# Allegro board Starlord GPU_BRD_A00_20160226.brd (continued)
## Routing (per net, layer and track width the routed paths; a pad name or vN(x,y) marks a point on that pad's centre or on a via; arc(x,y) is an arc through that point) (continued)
PWR_VGA_CORE_LGATE2: length 13.8
  TOP w0.254: v3(29.23,9.22) 29.23,9.81 29.2,9.83 v1(29.2,9.88)
  TOP w0.762: PU8206.8 v3(27.89,18.85)
  L6 w0.508: v3(29.23,9.22) 29.17,9.27
  L6 w1.016: v3(27.89,18.85) v3(27.89,13.26) 28.01,13.15 28.01,12.89 29.17,11.73 29.17,9.27
  BOTTOM w0.203: PU8201.17 29.44,8.89 29.23,9.1 v3(29.23,9.22)
  BOTTOM w0.762: PU8208.8 v3(27.89,13.26)
PWR_VGA_CORE_PHASE1: length 10.3
  L6 w1.016: v3(31.28,8.16) 31.8,8.16 35.85,12.21 v3(35.85,12.88)
  BOTTOM w0.203: v3(31.28,8.16) 31.23,8.1 PU8201.20
  BOTTOM w0.508: v3(31.28,8.16) 32.15,9.02 32.19,9.02 32.52,9.35 PC8211.2
  vias: v1(35.22,24.06) v3(32.88,24.18) v3(32.96,23.22) v3(32.93,22.28) v3(32.96,21.21) v3(33.01,20.17) v3(37.58,24.13) v3(37.58,23.24) v3(37.63,22.3) v3(37.68,21.26) v3(37.66,20.3)
PWR_VGA_CORE_PHASE2: length 10.4
  L6 w1.016: v3(28.25,8.02) 26.51,9.76 26.51,10.44 v3(24.02,12.93)
  BOTTOM w0.203: PU8201.16 28.34,8.1 v3(28.25,8.02)
  BOTTOM w0.508: v3(28.25,8.02) 28.25,8.07 28.26,8.08 28.26,8.4 27.4,9.27 27.4,9.35 26.69,10.06 PC8216.2
  vias: v1(24.04,23.93) v3(21.88,24.06) v3(21.88,23.04) v3(21.88,22.03) v3(21.88,21.14) v3(21.88,20.12) v3(26.71,23.8) v3(26.71,22.79) v3(26.71,21.77) v3(26.71,20.88) v3(26.71,19.87)
PWR_VGA_CORE_PSI: length 5.4
  TOP w0.254: v1(31.84,6) 32.45,6 v2(32.48,6.02) 32.71,6.02 32.76,6.07 PC8226.2 PR8259.1 PR8257.2 PR8258.2
  BOTTOM w0.203: PU8201.4 32.35,6.15 v2(32.48,6.02)
PWR_VGA_CORE_REFADJ: length 3.2
  TOP w0.254: v2(31.74,4.3) 32.07,4.63 v1(32.58,4.63)
  BOTTOM w0.203: 31.41,4.63 31.04,5 PU8201.6
  BOTTOM w0.254: PR8222.1 v2(31.74,4.3) 31.41,4.63
PWR_VGA_CORE_REFIN: length 4.4
  TOP w0.254: v1(31.28,4.75) v2(30.65,4.12) 30.85,3.91 PR8209.1 PC8204.1
  BOTTOM w0.254: PR8209.1 30.85,3.91 v2(30.65,4.12) 30.48,4.29 30.43,4.29 30.24,4.48 PU8201.7
PWR_VGA_CORE_RGND: length 14.9
  TOP w0.254: v2(28.36,4.5) 28.36,3.96 28.16,3.76 28.16,3.28 v1(28.16,3.28) 28.16,3.28 28.16,3.06 28.67,2.55 PC8201.1 PC8204.2 PR8209.2 PC8223.2
  BOTTOM w0.254: PR8220.1 22.91,7.69 PR8213.1 PC8217.1 PC8219.2 23.57,4.5 23.92,4.5 24.3,4.12 26.62,4.12 27.1,4.6 27.84,4.6 27.85,4.59 28.26,4.59 v2(28.36,4.5) 28.86,5 PU8201.10
PWR_VGA_CORE_SS: length 2.5
  TOP w0.254: v1(27.04,5.11) 27.07,5.13 v2(27.6,5.13) 27.6,5.78 PC8205.1
  BOTTOM w0.203: PU8201.11 28.03,5.75 27.6,5.32 v2(27.6,5.13)
PWR_VGA_CORE_TON: length 2.6
  TOP w0.254: v1(28.87,4.93) 29.05,4.75 v2(29.05,4.17)
  BOTTOM w0.254: PR8201.2 29.07,4.14 v2(29.05,4.17) 29.12,4.17 29.44,4.48 PU8201.9
PWR_VGA_CORE_TON_1: length 2.7
  BOTTOM w0.254: PR8202.2 28.25,1.57 v1(28.23,1.55) ; PR8202.2 PC8202.2 ; PR8202.2 28.29,2.44 28.96,2.44 PR8201.1
PWR_VGA_CORE_UGATE1: length 17.8
  TOP w0.305: v1(31.92,7.22) v3(32.65,7.22)
  TOP w0.762: PU8204.1 v3(37.8,13.07)
  L6 w1.016: v3(37.8,18.85) v3(37.8,13.07) 37.8,12.36 v3(32.65,7.22)
  BOTTOM w0.203: PU8201.2 32.39,6.95 v3(32.65,7.22)
  BOTTOM w0.762: PU8202.1 v3(37.8,18.85)
PWR_VGA_CORE_UGATE2: length 17.8
  TOP w0.254: v1(27.22,7.8) v3(27.22,7.14)
  TOP w0.762: v3(21.88,18.85) 21.87,18.84 PU8206.1
  L6 w1.016: 22.29,13.2 v3(22.28,13.19) ; 22.29,13.2 22.29,12.86 25.03,10.12 25.03,9.33 v3(27.22,7.14) ; 22.29,13.2 22.29,18.44 v3(21.88,18.85)
  BOTTOM w0.203: v3(27.22,7.14) 27.41,6.95 PU8201.14
  BOTTOM w0.762: PU8208.1 22.28,13.77 v3(22.28,13.19)
PWR_VGA_CORE_VID: length 4.3
  BOTTOM w0.203: 32.27,5.49 32.01,5.75 PU8201.5
  BOTTOM w0.254: 32.27,5.49 33.06,4.7 PC8203.2 PR8207.2 33.42,3.82 v1(33.42,2.92)
PWR_VGA_CORE_VREF: length 3.5
  TOP w0.254: PC8201.2 29.8,4.16 v2(29.84,4.16) 30.06,4.39 v1(30.06,4.68)
  BOTTOM w0.254: PR8206.1 29.96,4.04 v2(29.84,4.16) 29.84,4.17 29.96,4.17 29.84,4.3 PU8201.8
PWR_VGA_CORE_VSNS: length 8
  BOTTOM w0.254: PR8221.1 23.8,7.69 PR8212.2 PC8222.1 PC8219.1 23.95,5.01 24.13,5.01 24.51,4.63 v1(25.19,4.63) 26.41,4.63 27.6,5.82 27.6,5.95 27.8,6.15 PU8201.12
PWR_VGA_SNUB1: length 1.2
  BOTTOM w0.508: PC8206.1 32.68,12.39 PR8216.2
PWR_VGA_SNUB2: length 1.2
  BOTTOM w0.508: PR8215.2 27.43,12.5 PC8218.1
Q7601_G: length 5.7
  BOTTOM w0.102: Q7601.2 50.71,59.95 50.9,59.75 51.32,59.75 51.52,59.95 Q7601.5 53.05,59.95 53.33,60.23 v1(53.33,60.94) 53.33,61.59 53.05,61.87 R7657.2
REFIN_VREF: length 5.1
  TOP w0.254: PC8223.1 32.09,3.44 32.43,3.78 v2(32.43,3.84) 32.53,3.74 32.58,3.74 v1(33.04,3.28)
  BOTTOM w0.254: v2(32.43,3.84) 32.43,3.25 31.74,2.57 PR8222.2 PR8208.2 PR8206.2
RT8812_PVCC: length 3.5
  BOTTOM w0.203: PU8201.18 29.84,9.6 30.22,9.99 PR8223.2
  BOTTOM w0.508: PC8207.1 PR8223.2
SMBC_THERM_NV: length 22.2
  L3 w0.102: v2(50.08,61.45) 49.75,61.45 48.77,60.47 46.43,60.47 45.69,59.73 45.38,59.42 45.38,59.42 44.36,58.4 44.36,57.96 44.36,57.95 44.36,54.13 v2(43.96,53.73)
  BOTTOM w0.089: Q7601.1 49.81,59.3 49.01,60.1 v1(49.01,60.25) 49.01,60.38 v2(50.08,61.45) 50.19,61.45 50.74,61.99 50.74,62.4 RN7601.2 ; v2(43.96,53.73) 43.52,54.16 43.16,54.16 42.98,54.34 39.25,54.34 38.89,53.98 GPU1.D9
SMBD_THERM_NV: length 21.9
  TOP w0.089: v1(51.25,61.83) 51.25,61.8 v2(50.84,61.4)
  L3 w0.102: v2(38.19,54.38) 38.57,54.76 39.92,54.76 41.84,56.67 41.84,58.09 45.79,62.04 50.19,62.04 v2(50.84,61.4)
  BOTTOM w0.089: Q7601.4 51.51,60.6 50.84,61.27 v2(50.84,61.4) 50.97,61.4 51.37,61.8 RN7601.1 ; GPU1.D8 38.19,53.55 v2(38.19,54.38)
SML1_SMBCLK: length 74.8
  TOP w0.089: v1(51.78,58.65) 51.76,58.68 v2(51.17,58.68)
  L3 w0.102: v2(51.17,58.68) 51.17,53.17 50,52 50,45.14 45.63,40.77 45.63,40.77 45.32,40.46 41.29,40.46 40.88,40.05 36.69,40.05 35.59,41.14 31.38,41.14 30.94,40.69 28.12,40.69 27.41,39.98 18.84,39.98 16.73,42.1 16.73,44.48 14.32,46.88 11.8,46.88 9.48,49.2 9.48,51.15 8.89,51.73 7.07,51.73 6.12,52.68 4.26,52.68 v2(3.37,51.79)
  BOTTOM w0.089: GPU3.E3 3.55,51.98 v2(3.37,51.79) ; Q7601.6 52.06,58.91 51.86,58.7 51.2,58.7 v2(51.17,58.68)
SML1_SMBDATA: length 78.1
  TOP w0.089: v1(51.7,60.25) v2(51.11,60.25)
  L3 w0.102: v2(51.11,60.25) 51.11,60.14 50.66,59.69 50.66,53.41 49.47,52.22 49.47,45.37 45.1,40.99 41.07,40.99 40.66,40.58 37.91,40.58 36.46,42.03 31.52,42.03 30.72,41.23 27.9,41.23 27.36,40.69 18.89,40.69 17.26,42.32 17.26,44.7 14.55,47.42 12.13,47.42 10.01,49.53 10.01,51.37 9.11,52.26 8.43,52.26 7.29,52.26 6.34,53.22 3.95,53.22 3.01,52.28 1.84,52.28 v2(1.79,52.23)
  BOTTOM w0.089: v2(1.79,52.23) 1.84,52.23 2.17,51.9 2.77,51.9 2.95,52.08 GPU3.E2 ; Q7601.3 50.81,60.6 51.11,60.3 v2(51.11,60.25)
SP_PLLVDD: length 9.8
  TOP w0.508: v2(32.37,51.06) 32.3,51.13 C7601.1
  TOP w1.016: 32.15,49.26 33.11,48.29 33.11,45.95 34.13,44.94 v3(34.13,44.81)
  BOTTOM w0.762: L7602.2 33.95,42.19 C7604.1 C7603.1 34.23,44.71 v3(34.13,44.81)
  vias: v1(32.53,49.94) v2(31.54,51.84)
STRAP0: length 5.3
  TOP w0.127: v2(39.01,46.42) 39.09,46.5 R7619.2
  BOTTOM w0.127: GPU1.D1 38.6,46.86 39.01,46.45 v2(39.01,46.42) 38.01,45.42 R7608.1
STRAP1: length 7.4
  TOP w0.127: v2(37.56,45.47) 37.56,45.54 36.77,46.32 36.77,47.41 R7609.2
  BOTTOM w0.127: R7611.1 v1(37.18,44.89) 37.2,44.91 37.2,45.12 v2(37.56,45.47) 38.31,46.22 38.31,47.05 38.24,47.12 38.24,47.58 38.6,47.94 GPU1.D2
STRAP2: length 8.5
  TOP w0.127: R7614.2 37.21,47.4 37.21,46.47 v2(37.58,46.11)
  BOTTOM w0.127: R7615.1 36.34,44.88 37.39,45.94 37.41,45.94 v2(37.58,46.11) 37.59,46.11 38.05,46.57 38.05,46.95 37.99,47.01 37.99,47.69 38.17,47.87 38.17,49.38 GPU1.E4
STRAP3: length 8.2
  TOP w0.127: R7625.2 35.82,47.55 35.82,45.94 v2(36.19,45.57)
  BOTTOM w0.127: R7626.1 35.5,44.78 35.58,44.86 v1(35.58,44.89) 35.6,44.89 36.19,45.47 v2(36.19,45.57) 36.32,45.71 36.34,45.71 37.21,46.58 37.21,47.18 37.33,47.29 37.33,48.58 GPU1.E3
STRAP4: length 8.7
  TOP w0.127: R7628.2 39.53,48.03 39.53,46.04 v2(39.21,45.72)
  BOTTOM w0.127: R7629.1 38.85,45.37 v2(39.21,45.72) 39.46,45.98 39.46,46.71 38.99,47.18 38.99,48.61 GPU1.D3
STRAP_REF0_GND_N9: length 2.8
  TOP w0.127: v1(36.79,49.79) 36.68,49.9 R7607.2 36.71,51.11 36.71,51.69 v2(36.5,51.9)
  BOTTOM w0.127: v2(36.5,51.9) GPU1.F6
SYS_PEX_RST_MON#: length 10.7
  BOTTOM w0.127: v1(20.79,38.87) 20.81,38.88 R7304.2 R7313.1 21.62,40.22 22.2,40.81 23.46,40.81 D7301.2 24.03,42.3 23.78,42.55 U7301.4 21.87,43.47 R7634.2 R7306.1
SYS_PEX_RST_MON_GPU#: length 27.3
  TOP w0.127: v2(37.4,54.37) 37.39,54.38 36.81,54.38 R7643.1
  L3 w0.127: v2(22.09,44.78) 22.88,44 28.62,44 29.66,45.04 31.37,45.04 32.48,46.14 32.72,46.14 35.52,48.95 35.52,50.84 35.09,51.27 35.09,54.33 35.55,54.79 36.98,54.79 v2(37.4,54.37)
  BOTTOM w0.127: GPU1.E9 37.8,53.99 37.42,54.37 v2(37.4,54.37) ; v2(22.09,44.78) 22.33,44.54 R7634.1 22.38,43.95 v1(23.26,43.95)
TESTMODE: length 7.7
  BOTTOM w0.102: GPU1.AD9 21.6,54.38 21.04,54.38 20.82,54.61 20.82,54.92 20.61,55.12 20.26,55.12 20.26,55.12 19.74,55.12 19.74,55.12 19.46,55.12 19.46,55.12 19.22,55.12 v1(17.11,57.23) 16.25,58.09 R7302.1
TP_VPPNC3: length 2.5
  TOP w0.102: VRAM2.A5 40.17,92.17 TP7803.1
TP_VPPNC4: length 4.7
  TOP w0.102: VRAM2.U5 40,79.26 40.33,79.58 v2(40.43,79.58)
  BOTTOM w0.102: v2(40.43,79.58) 42.03,77.98 42.03,76.15 TP7804.1
TP_VPPNC5: length 4.1
  TOP w0.102: v2(23.51,77.42) 22.85,77.42 21.97,78.3 21.97,79.17 VRAM3.A5
  BOTTOM w0.102: TP7901.1 23.21,77.12 v2(23.51,77.42)
TP_VPPNC6: length 2.8
  TOP w0.102: TP7902.1 22,94.78 VRAM3.U5
TP_VPPNC7: length 2.8
  BOTTOM w0.102: VRAM4.A5 22,94.78 TP7903.1
TP_VPPNC8: length 3
  BOTTOM w0.102: TP7904.1 21.97,76.24 21.97,79.17 VRAM4.U5
VGA_CORE: length 52.9
  L3 w0.508: v2(37.51,9.73) 37.51,9.71 37.63,9.58 37.63,6.42 36.27,5.06 34.64,5.06 32.78,3.2 27.62,3.2 26.41,4.41 26.41,5.52 24.6,7.32 v2(24.6,7.62)
  L6 w0.508: v2(37.51,9.73) 37.73,9.5 39.11,9.5 39.94,10.34 39.94,11.57 40.71,12.33 40.71,18.8 41.09,19.18 41.09,33.02 40.5,33.61 v2(37.02,33.61)
  BOTTOM w0.508: PR8309.1 37.43,11.01 37.43,10.1 37.51,10.02 v2(37.51,9.73) ; v2(24.6,7.62) 24.6,7.02 PR8212.1
  vias: v1(19.6,48.44) v1(20.69,37.54) v1(24.09,48.42) v1(24.68,58.73) v1(28.69,37.67) v1(29.92,48.8) v1(34.46,37.6) v2(25.75,54.44) v2(26.76,54.51) v2(26.71,53.6) v2(26.84,60.71) v2(26.88,58.67) v2(26.88,56.64) v2(26.94,52.99) v2(28.79,60.68) v2(28.77,58.65) v2(28.77,56.62) v2(28.79,53.01) v2(28.82,62.51) v2(28.82,54.46) v2(28.82,53.65) v2(30.8,58.65) v2(30.75,54.54) v2(30.75,53.67) v2(30.7,53.04) v2(30.8,62.51) v2(30.8,60.73) v2(30.81,56.66) v2(32.78,58.65) v2(32.78,54.49) v2(32.81,60.73) v2(32.83,56.62) v2(33.78,53.65) v2(34.69,58.6) v2(34.79,60.68) v2(34.72,56.59) v3(16.7,34.55) v3(16.73,33.35) v3(17.62,35.51) v3(17.62,34.52) v3(17.64,33.33) v3(18.68,33.35) v3(18.66,32.24) v3(18.86,48.47) v3(19.73,33.35) v3(19.7,32.24) v3(20.64,33.33) v3(20.61,32.21) v3(21.17,46.33) v3(21.76,35.84) v3(21.76,34.98) v3(21.76,34.06) v3(21.78,33.23) v3(22.06,46.33) v3(22.67,35.84) v3(22.67,34.98) v3(22.67,34.06) v3(22.7,33.23) v3(23.74,35.84) v3(23.74,34.98) v3(23.74,34.06) v3(23.76,33.23) v3(24.65,35.82) v3(24.65,34.95) v3(24.65,34.04) v3(24.68,33.2) v3(25.42,46.66) v3(25.67,45.77) v3(25.64,35.84) v3(25.64,34.98) v3(25.64,34.06) v3(25.67,33.23) v3(26.28,46.61) v3(26.56,45.77) v3(26.56,35.82) v3(26.56,34.95) v3(26.56,34.04) v3(26.58,33.2) v3(27.12,46.61) v3(27.42,45.8) v3(27.47,35.82) v3(27.47,34.95) v3(27.47,34.04) v3(27.5,33.2) v3(27.96,46.61) v3(28.26,45.8) v3(28.39,35.79) v3(28.39,34.93) v3(28.39,34.01) v3(28.41,33.18) v3(28.79,46.56) v3(29.12,45.77) v3(29.33,35.77) v3(29.35,34.9) v3(29.35,34.04) v3(29.38,33.2) v3(29.63,46.56) v3(29.99,45.77) v3(30.27,35.74) v3(30.34,34.88) v3(30.37,34.04) v3(30.34,33.2) v3(30.57,46.56) v3(30.88,45.77) v3(31.44,35.77) v3(31.46,34.9) v3(31.46,34.04) v3(31.49,33.2) v3(31.56,46.56) v3(32.38,35.77) v3(32.45,34.9) v3(32.48,34.06) v3(32.45,33.23) v3(33.59,33.3) v3(34.51,33.28) v3(35.45,33.3)
VGA_CORE_DISCHG: length 1.4
  BOTTOM w0.102: PQ8305.3 36.52,10.99 PR8309.2
VGA_CORE_PSI: length 51.8
  TOP w0.127: PR8257.1 35.2,7.82 v1(35.35,7.67) 35.96,7.06 v2(35.96,6.96)
  L6 w0.127: v2(41.24,44.15) 41.19,44.15 40.8,43.75 40.8,39.54 41.61,38.73 41.61,34.33 42.55,33.39 42.55,28.83 42.9,28.48 42.9,21.2 42.9,20.06 42.32,19.47 42.32,18.67 41.94,18.29 41.94,11.82 41.44,11.32 41.18,11.06 41.18,9.55 39.57,7.94 38.18,7.94 37.2,6.96 v2(35.96,6.96)
  BOTTOM w0.127: v2(41.24,44.15) 41.24,45.39 41.62,45.77 41.62,48.18 41.86,48.41 41.86,48.91 41.34,49.42 40.58,49.42 GPU1.B4
VGA_CORE_VID: length 60.9
  TOP w0.089: v1(34.33,2.47) 34.33,2.78 34.05,3.06 v2(34.05,3.13)
  L3 w0.102: v2(35.4,46.87) 35.42,46.87 35.65,47.09 35.65,48.26 36.52,49.13 36.52,50.33 37.32,51.14 v2(37.32,51.87)
  L6 w0.102: v2(35.4,46.87) 35.4,46.64 35.36,46.61 35.36,45.85 35.78,45.43 35.78,45.4 37.57,43.62 39.51,43.62 40.27,42.85 40.27,39.32 41.09,38.51 41.09,34.12 42.03,33.18 42.03,28.62 42.38,28.26 42.38,20.27 41.8,19.69 41.8,18.89 41.42,18.5 41.42,12.04 40.66,11.28 40.66,9.77 39.35,8.46 36.72,8.46 35.42,7.17 35.42,5.24 34.05,3.87 v2(34.05,3.13)
  BOTTOM w0.089: v2(37.32,51.87) 37.34,51.9 37.4,51.9 GPU1.E7 ; v2(34.05,3.13) 34.05,3.57 PR8207.1
VGACORE_GND_SENSE_1: length 92.9
  TOP w0.203: v2(23.15,10.09) 23.18,10.11 v1(23.18,10.67)
  L6 w0.203: v2(23.15,10.09) 23.18,10.09 23.66,9.6 23.66,5.87 24.73,4.8 24.94,4.8 27.85,1.9 39.79,1.9 42.65,4.75 44.78,4.75 46.68,6.65 52.3,6.65 53.13,7.48 53.13,31.32 52.36,32.08 52.36,37.95 49.98,40.34 45.1,40.34 41.9,43.54 41.9,44.39 41.61,44.68 37.23,44.68 36.64,45.27 36.64,45.8 v2(36.24,46.2)
  BOTTOM w0.203: v2(23.15,10.09) 22.62,9.55 22.62,9 PR8220.2 ; GPU1.F1 36.9,47.05 36.69,46.84 36.69,46.55 36.43,46.28 36.32,46.28 v2(36.24,46.2)
VGACORE_VDD_SENSE_1: length 93.5
  TOP w0.203: v1(23.79,9.4) 23.21,9.4 v2(23.18,9.38)
  L6 w0.203: v2(36.23,46.84) 36.41,46.66 36.43,46.66 36.97,46.12 36.97,45.41 37.37,45.01 41.75,45.01 42.23,44.53 42.23,43.68 45.24,40.67 50.11,40.67 52.7,38.09 52.7,32.22 53.46,31.46 53.46,7.34 52.44,6.32 46.82,6.32 44.92,4.42 42.79,4.42 39.93,1.57 27.71,1.57 24.81,4.47 24.59,4.47 23.33,5.73 23.33,9.22 v2(23.18,9.38)
  BOTTOM w0.203: GPU1.F2 36.51,47.81 36.51,47.16 36.24,46.89 36.24,46.84 v2(36.23,46.84) ; v2(23.18,9.38) 23.51,9.38 23.87,9.02 PR8221.2
VIDEO_CLK_XTAL_SS: length 3.4
  BOTTOM w0.089: GPU1.A10 42.63,54.78 42.64,54.77 43.19,54.77 v1(43.32,54.64) 43.37,54.64 43.56,54.45 43.93,54.45 44,54.38 R7601.1
VIDEO_THERM_OVERT#: length 1.6
  BOTTOM w0.127: TP7606.1 29.57,43.38 Q7602.6
VPP1: length 3.4
  BOTTOM w0.102: VRAM1.A5 40.81,78.39 TP7801.1
VPP2: length 2.8
  BOTTOM w0.102: VRAM1.U5 40.22,92.22 TP7802.1

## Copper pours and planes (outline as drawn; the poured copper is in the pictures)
3V3_AON_S0 on TOP: 45.86,34.75 44.24,36.38 44.24,38.91 44.36,39.03 45.8,39.03 46.63,38.2 47.21,38.2 47.72,37.7 47.72,34.9 47.56,34.75
3V3_AON_S0 on TOP: 23.13,50.45 23.1,50.47 23.1,52.48 24.42,53.8 25.14,53.8 25.42,53.52 25.42,50.55 25.31,50.45 ; 4 cut-outs
3V3_AON_S0 on BOTTOM: 44.62,36 44.24,36.38 44.24,38.81 44.53,39.1 45.62,39.1 46.28,38.44 46.28,38.2 47.21,38.2 47.72,37.7 47.72,36.05 47.67,36
3V3_AON_S0 on L4: 45.84,37.8 46.14,38.1 46.14,40.21 41.99,44.36 33.95,44.36 33.94,44.37 32.69,44.37 32.04,45.01 25.19,45.01 24.68,45.52 24.68,52.02 25.21,52.56 25.21,53.85 25.01,54.05 23.87,54.05 22.65,52.84 22.65,42.35 23.66,41.33 32.93,41.33 33.7,40.57 40.43,40.57 41.65,39.35 42.38,39.35 43.93,37.8
5V_S0 on BOTTOM: 6.8,41.86 6.8,42.42 7.91,43.54 8.32,43.54 8.45,43.41 8.45,42.22 8.09,41.86
GND on TOP: 25.62,53.93 25.31,54.23 25.31,55.53 25.62,55.83 34.58,55.83 34.74,55.98 35.04,55.98 35.32,56.26 35.32,57.1 35.3,57.13 25.36,57.13 25.16,56.92 25.16,56.16 25.19,56.14 25.19,55.27 24.86,54.94 23.94,54.94 23.76,55.12 23.76,56.06 24.45,56.75 24.45,57.18 25.31,58.04 35.7,58.04 36.01,57.74 36.01,55.65 35.75,55.4 35.37,55.4 35.14,55.17 35.14,54.77 35.07,54.69 34.53,54.69 33.77,53.93 ; 5 cut-outs
GND on TOP: 25.39,59.49 25.24,59.64 25.24,60.23 25.36,60.35 35.14,60.35 35.22,60.43 35.91,60.43 35.93,60.4 35.93,59.92 35.5,59.49 ; 1 cut-out
GND on TOP: 51.99,0.51 26,0.51 25.65,0.65 25.51,1 25.51,2 25.07,3.07 24,3.51 22.3,3.51 21.25,3.95 20.81,5 20.81,11.3 20.07,13.07 18.3,13.81 13,13.81 11.95,14.25 11.51,15.3 11.51,25.5 10.77,27.27 9,28.01 3,28.01 1.24,28.74 0.51,30.5 0.51,93.5 1.24,95.26 3,95.99 52,95.99 53.76,95.26 54.49,93.5 54.49,3.82 54.49,3.82 54.49,3 53.76,1.24 52,0.51 ; 48 cut-outs
GND on TOP: 23.21,49.15 23,49.36 23,49.84 23.18,50.02 25.29,50.02 25.67,50.4 25.67,51.84 25.64,51.87 25.64,52.89 25.8,53.04 26.33,53.04 26.83,52.54 30.41,52.54 31,51.95 31,49.51 30.65,49.15 ; 9 cut-outs
GND on TOP: 28.87,13.14 28.62,13.39 28.62,13.52 28.36,13.77 27.47,13.77 27.35,13.9 27.35,17.2 28.49,17.2 28.62,17.33 28.62,18.34 32.17,18.34 32.3,18.22 32.3,15.04 31.28,15.04 31.03,14.79 31.03,13.26 30.9,13.14
GND on BOTTOM: 10.59,32.69 10.13,33.15 10.13,37.89 10.35,38.1 11.32,38.1 11.34,38.13 14.19,38.13 14.7,37.62 14.7,34.22 13.17,32.69
GND on BOTTOM: 29,5.64 28.95,5.69 28.95,7.45 28.97,7.47 30.67,7.47 30.72,7.42 30.72,5.67 30.7,5.64
GND on BOTTOM: 37.7,3.33 37.53,3.5 37.53,5.6 37.58,5.64 38.76,5.64 39.12,5.28 39.12,3.33
GND on BOTTOM: 1.79,43.41 1.46,43.74 1.46,47.37 1.87,47.78 7.1,47.78 7.48,47.4 7.48,43.77 7.13,43.41
GND on BOTTOM: 4.33,73.18 4.28,73.23 4.28,74.93 4.33,74.98 6.95,74.98 7,74.93 7,73.26 6.92,73.18
GND on BOTTOM: 47.67,9.73 47.54,9.86 47.54,13.14 48.05,13.64 48.05,15.07 47.97,15.14 47.77,15.14 47.67,15.24 47.67,16.18 47.69,16.21 48.66,16.21 48.68,16.18 48.68,15.19 48.76,15.12 48.76,13.67 49.34,13.08 49.34,10.82 49.16,10.65 49.16,9.96 48.94,9.73 ; 2 cut-outs
GND on BOTTOM: 41.65,22.03 41.6,22.08 41.6,27.26 41.77,27.44 43.55,27.44 43.68,27.31 43.68,22.15 43.55,22.03
GND on BOTTOM: 13.1,14.99 12.72,15.37 12.72,25.96 13.53,26.77 16.91,26.77 17.62,26.06 17.62,24.34 16.83,23.55 15.97,23.55 15.89,23.47 15.89,22.84 15.23,22.18 15.23,15.24 14.98,14.99 ; 1 cut-out
GND on BOTTOM: 44.9,55.83 44.85,55.88 44.85,57.2 44.95,57.31 45.38,57.31 45.43,57.25 45.43,56.44 45.48,56.39 45.89,56.39 46.09,56.19 46.09,55.91 46.01,55.83
GND on BOTTOM: 37.76,33.94 37.1,34.6 37.1,37.44 37.56,37.9 42.54,37.9 42.89,37.54 42.89,34.12 42.71,33.94
GND on BOTTOM: 32.7,53.45 32.58,53.57 32.58,53.83 35.05,56.3 35.05,56.8 34.9,56.95 34.55,56.95 31.48,53.88 31.18,53.88 31.01,54.04 31.01,54.3 35.07,58.36 35.07,58.78 34.92,58.93 34.5,58.93 29.47,53.9 29.17,53.9 29.02,54.06 29.02,54.21 35.1,60.29 35.1,60.79 35,60.89 34.43,60.89 27.37,53.83 27.24,53.83 26.99,54.08 26.99,54.21 34.31,61.53 34.98,61.53 35.24,61.28 35.24,55.61 33.08,53.45
GND on BOTTOM: 51.76,33.1 51.45,33.4 51.45,34.29 51.22,34.52 50.66,34.52 50.21,34.98 46.52,34.98 46.09,34.55 45.58,34.55 45.43,34.39 45.43,33.79 45.3,33.66 43.86,33.66 43.58,33.94 43.58,36.1 43.85,36.37 44.06,36.37 44.33,36.1 44.36,36.1 44.87,35.59 46.17,35.59 46.4,35.82 53.1,35.82 53.58,35.33 53.58,33.3 53.38,33.1 ; 3 cut-outs
GND on BOTTOM: 41.19,10.37 41.01,10.54 41.01,18.49 41.04,18.52 42.54,18.52 42.76,18.29 42.76,10.65 42.48,10.37 ; 1 cut-out
GND on BOTTOM: 26.23,54.84 25.97,55.1 25.97,55.23 32.83,62.08 32.83,62.21 32.45,62.59 32.2,62.59 26.48,56.88 26.23,56.88 26.1,57 26.1,57.26 31.12,62.28 31.12,62.7 30.92,62.91 30.61,62.91 26.48,58.78 26.23,58.78 25.97,59.04 25.97,59.16 29.19,62.38 29.19,62.68 29.01,62.86 28.5,62.86 28.36,62.71 28.36,62.69 26.48,60.81 26.23,60.81 25.97,61.07 25.97,61.19 27.69,62.91 33.41,62.91 33.69,62.63 33.69,62.06 26.48,54.84
GND on BOTTOM: 28.87,13.14 28.62,13.39 28.62,14.79 28.36,15.04 27.35,15.04 27.35,18.34 30.9,18.34 31.16,18.09 31.16,17.2 31.28,17.07 32.3,17.07 32.3,13.77 31.41,13.77 31.16,13.52 31.16,13.26 31.03,13.14
GND on BOTTOM: 34.05,4.4 34.03,4.42 34.03,4.8 33.7,5.13 33.57,5.13 33.44,5.26 33.44,5.52 33.57,5.64 34.05,5.64 34.66,5.03 34.66,4.52 34.53,4.4
GND on L2GND, L7GND: 26,0.51 25.65,0.65 25.51,1 25.51,2 25.07,3.07 24,3.51 22.3,3.51 21.25,3.95 20.81,5 20.81,11.3 20.07,13.07 18.3,13.81 13,13.81 11.95,14.25 11.51,15.3 11.51,25.5 10.77,27.27 9,28.01 3,28.01 1.24,28.74 0.51,30.5 0.51,93.5 1.24,95.26 3,95.99 52,95.99 53.76,95.26 54.49,93.5 54.49,3 53.76,1.24 52,0.51
GND on L3: outline of 81 points within 0.51,0.51 54.49,95.99
GND on L3: 45.25,52.58 45.25,58.27 45.91,58.93 48.94,58.93 49.55,58.32 49.55,54.61 49.32,54.38 48.12,54.38 47.62,53.88 47.62,53.06 46.78,52.23 45.61,52.23
GND on L4: 32.81,44.5 40.3,44.5 40.68,44.89 40.68,46.03 40.3,46.41 39.79,46.41 37.38,48.82 35.98,48.82 32.55,45.39 32.55,44.76
GND on L4: outline of 122 points within 0.51,0.51 54.49,95.99
GND on L4: 12.61,40.44 18.33,40.44 20.11,42.22 20.11,53.78 19.6,54.28 17.69,54.28 11.98,60 11.6,60 11.34,59.74 11.34,59.49 11.47,59.36 11.47,54.92 10.71,54.16 10.71,49.71 11.85,48.57 11.85,41.2
GND on L5VCC: 26,0.51 25.65,0.65 25.51,1 25.51,2 25.07,3.07 24,3.51 22.3,3.51 21.25,3.95 20.81,5 20.81,11.3 20.07,13.07 18.3,13.81 13,13.81 11.95,14.25 11.51,15.3 11.51,25.5 10.77,27.27 9,28.01 3,28.01 1.24,28.74 0.51,30.5 0.51,93.5 1.24,95.26 3,95.99 52,95.99 53.76,95.26 54.49,93.5 54.49,3 53.76,1.24 52,0.51 ; 1 cut-out
GND on L6: outline of 100 points within 0.51,0.51 54.49,95.99 ; 1 cut-out
VCC1R05VIDEO_PEX_PLLVDD on BOTTOM: 24.07,57.89 23.79,58.17 23.79,58.75 24.2,59.16 24.58,59.16 24.73,59.01 24.73,58.04 24.58,57.89
(no net) on L3: 30.5,64.82 31.65,64.82 31.75,64.73 31.75,64.03 31.85,63.94 34.59,63.94 34.63,63.98 34.63,63.97 35.03,63.97 35.28,64.23 35.28,64.43 35.49,64.63 35.89,64.63 36.31,64.21 36.31,61.4 36.83,60.88 36.83,59.17 36.72,59.07 36.15,59.07 35.14,60.08 35.14,60.94 33.74,62.34 31.89,62.34 31.21,63.02 27.96,63.02 25.21,60.28 18,60.28 16.14,62.13 16.14,64.39 18.53,66.78 22.52,66.78 25.16,64.14 29.81,64.14
1D05V_PWR on BOTTOM: 3.6,62.16 3.27,62.49 3.27,67.16 4.08,67.97 6.21,67.97 7.71,66.48 8.04,66.48 8.17,66.35 8.17,62.41 7.91,62.16 ; 3 cut-outs
1D05V_VGA_EN# on BOTTOM: 38.22,1.43 37.48,2.16 37.48,3.2 38.65,3.2 39.11,2.75 39.87,2.75 39.94,2.67 39.94,2.21 39.16,1.43 ; 1 cut-out
1D05V_VGA_S0 on TOP: 23.13,59.39 22.34,60.18 11.32,60.18 11.14,60.35 11.14,63.66 11.24,63.76 14.26,63.76 17.21,66.7 20.27,66.7 20.77,66.21 22.1,66.21 22.11,66.22 22.6,66.22 24.42,64.39 24.42,59.64 24.17,59.39 ; 3 cut-outs
1D05V_VGA_S0 on BOTTOM: 11.47,60.02 10.99,60.51 9.95,60.51 9.44,61.01 9.31,61.01 8.68,61.65 8.68,65.33 8.93,65.59 11.34,65.59 13.07,63.86 13.07,60.35 12.74,60.02 ; 5 cut-outs
1D05V_VGA_S0 on BOTTOM: 24.2,54.59 23.99,54.79 23.99,57.56 24.17,57.74 24.58,57.74 24.78,57.94 24.78,59.19 24.65,59.31 24.12,59.31 23.99,59.44 23.99,64.16 19.8,68.35 19.27,68.35 19.01,68.1 19.01,66.27 18.48,65.74 17.03,65.74 16.93,65.84 16.93,67.67 19.04,69.78 19.83,69.78 20.59,69.02 21.22,69.02 21.4,68.84 21.4,68.08 21.81,67.67 22.01,67.67 25.36,64.32 25.36,54.74 25.21,54.59
1D05V_VGA_S0 on L4: 17.72,54.82 12.16,60.38 11.14,60.38 10.98,60.54 10.98,65.83 12.26,67.11 16.6,67.11 17.19,67.69 22.62,67.69 23.31,67.01 23.31,65.87 22.95,65.51 16.8,65.51 16.27,64.98 16.27,62.16 18.48,59.95 24.96,59.95 25.14,59.77 25.14,55.02 24.93,54.82
1D35V_PWR on BOTTOM: 44.69,22.3 43.86,23.14 43.86,28.17 44.06,28.38 44.49,28.38 44.72,28.15 51.43,28.15 51.6,27.97 51.6,27.64 51.09,27.13 51.09,22.69 50.71,22.3 ; 1 cut-out
1D35V_VGA_S0 on TOP: 11.14,75.06 10.96,75.24 10.96,76.41 11.27,76.71 11.27,80.29 11.34,80.37 11.83,80.37 12.18,80.72 12.18,81.94 12.82,82.58 13.33,82.58 13.66,82.25 13.66,75.39 13.33,75.06 ; 4 cut-outs
1D35V_VGA_S0 on TOP: 11.17,87.43 10.99,87.61 10.99,94.29 10.96,94.31 10.96,94.8 11.22,95.05 14.14,95.05 14.39,94.8 14.39,94.03 14.14,93.78 13.38,93.78 12.97,93.37 12.97,87.79 12.61,87.43 ; 13 cut-outs
1D35V_VGA_S0 on TOP: 33.34,86.24 33.21,86.36 33.21,87 32.91,87.3 32.91,93.68 33.06,93.83 34.2,93.83 34.97,93.07 34.97,86.49 34.71,86.24 ; 13 cut-outs
1D35V_VGA_S0 on TOP: 46.14,28.98 45.96,29.16 45.96,31.27 46.57,31.88 49.32,31.88 50.54,33.1 50.54,39.75 49.93,40.36 49.93,42.27 50.54,42.88 50.54,43.87 51.2,44.53 52.82,44.53 53.15,44.2 53.15,29.95 52.19,28.98
1D35V_VGA_S0 on TOP: 35.35,60.81 34.64,61.52 34.64,63 34.76,63.12 35.78,63.12 36.06,62.84 36.06,60.94 35.93,60.81 ; 2 cut-outs
1D35V_VGA_S0 on TOP: 32.02,65.74 31.59,66.17 31.59,69.57 29.89,71.28 28.79,71.28 27.14,72.93 27.14,75.59 26.18,76.56 26.18,84.79 26.58,85.19 28.59,85.19 28.87,84.92 28.87,84.13 29.15,83.85 29.15,77.8 29.59,77.36 32.87,77.36 33.01,77.5 33.01,82.76 33.24,82.99 33.24,83.54 35.37,83.54 35.37,77.96 41.52,71.81 41.52,69.4 42.61,68.3 42.61,68.08 42.51,67.97 42.26,67.97 41.82,68.41 41.29,68.41 40.96,68.08 38.17,68.08 38.01,68.23 37.96,68.23 37.81,68.38 37.81,69.32 37.58,69.55 35.98,69.55 35.32,68.89 35.32,68.08 35.14,67.9 33.42,67.9 32.73,67.21 32.73,66.02 32.45,65.74 ; 24 cut-outs
1D35V_VGA_S0 on TOP: 32.12,62.92 32.07,62.97 32.07,63.88 32.17,63.99 32.68,63.99 32.86,64.16 32.86,64.39 33.19,64.72 34.13,64.72 34.33,64.52 34.33,64.11 34.2,63.99 33.65,63.99 33.31,63.66 33.31,63.43 32.81,62.92
1D35V_VGA_S0 on TOP: 25.11,62.74 24.63,63.22 24.63,64.19 24.76,64.32 26.08,64.32 26.58,63.81 27.55,63.81 27.97,63.39 27.97,62.8 27.9,62.74 ; 1 cut-out
1D35V_VGA_S0 on TOP: 47.67,58.86 47.03,59.49 47.03,76.03 48.91,77.91 48.91,83.49 49.16,83.75 50.84,83.75 51.12,83.47 51.12,76.23 51.63,75.72 52.9,75.72 53.61,75.01 53.61,60.61 52.36,59.36 49.82,59.36 49.32,58.86 ; 13 cut-outs
1D35V_VGA_S0 on TOP: 26.71,88.17 26.48,88.4 26.48,93.63 27.47,94.62 28.87,94.62 29.12,94.36 29.12,91.47 28.84,91.19 28.84,88.34 28.67,88.17 ; 9 cut-outs
1D35V_VGA_S0 on BOTTOM: 35.59,57.07 35.37,57.29 35.37,61.41 34.78,62 34.78,62.29 34.55,62.53 34,62.53 33.45,63.08 25.74,63.08 25.54,63.28 25.54,63.96 25.82,64.24 26.18,64.24 26.39,64.02 26.75,64.02 26.88,64.15 27.02,64.15 27.32,63.85 28.25,63.85 28.55,64.15 28.76,64.15 28.91,64 29.24,64 29.39,64.15 29.39,64.31 29.75,64.67 29.96,64.67 29.96,64.66 30.65,63.97 30.86,63.97 31.04,64.15 31.22,64.15 31.4,63.97 31.68,63.97 31.88,64.18 31.93,64.18 32.74,64.99 32.87,64.99 32.97,64.88 32.97,64.87 32.98,64.87 33.24,64.62 34.06,64.62 34.71,63.97 35.93,63.97 36.07,64.12 37.02,64.12 37.15,63.99 37.15,63.85 36.17,62.87 36.17,62.5 36.35,62.32 36.35,62.12 36.2,61.97 36.2,61.64 36.39,61.45 36.39,59.72 36.17,59.5 36.17,59.2 36.38,59 36.43,59 37.01,58.41 37.01,58.31 37.15,58.17 37.15,58 36.21,57.07
1D35V_VGA_S0 on BOTTOM: 44.67,28.32 44.57,28.43 44.57,30.99 44.82,31.25 50.59,31.25 50.76,31.07 50.76,28.5 50.59,28.32
1D35V_VGA_S0 on L3: 19.19,90.81 19.19,93.63 17.9,94.92 12.94,94.92 9.9,91.88 9.9,75.9 10.79,75.01 11.42,75.01 11.78,75.37 11.78,88.88 13.58,90.68 19.07,90.68
1D35V_VGA_S0 on L3: 46.14,31.25 46.14,29.26 46.55,28.86 52.09,28.86 53.48,30.25 53.48,44 53.47,44.01 53.47,93.06 51.35,95.18 48.17,95.18 47.92,94.92 47.92,93.78 51.35,90.35 51.35,62.92 51.73,62.54 51.73,51.74 50.84,50.85 50.84,45.16 48.1,42.42 48.1,34.88 49.29,33.68 49.29,32.44 48.63,31.78 46.68,31.78
1D35V_VGA_S0 on L6: 45.51,41.61 42.74,44.38 42.74,45.04 41.42,46.36 39.61,46.36 33.29,52.68 33.29,62.69 32.86,63.12 32.86,65.15 32.22,65.79 32.22,66.17 32.58,66.53 32.58,69.4 32.68,69.5 32.68,71.86 29.23,75.31 29.23,81.92 26.74,84.41 24.48,84.41 23.43,83.37 22.19,83.37 21.81,82.99 21.81,81.97 21.99,81.79 23.18,81.79 23.54,82.15 25.29,82.15 26.1,81.33 26.1,79.35 25.95,79.2 23.08,79.2 22.32,79.96 16.65,79.96 16.32,80.29 16.32,82.12 16.68,82.48 18.43,82.48 18.81,82.86 18.81,83.7 18.66,83.85 18.33,83.85 18.28,83.8 15.36,83.8 14.9,84.26 14.9,84.56 15.13,84.79 18.81,84.79 19.34,85.32 19.34,86.31 18.99,86.67 14.54,86.67 13.68,87.53 12.66,87.53 12.39,87.81 12.39,94.29 13.3,95.2 51.45,95.2 53.61,93.04 53.61,43.44 51.78,41.61 ; 1 cut-out
3D3V_S0 on BOTTOM: 1.41,39.68 1.23,39.86 1.23,43.03 1.44,43.23 6.26,43.23 6.52,42.98 6.52,41.71 6.72,41.51 7.94,41.51 8.12,41.33 8.12,39.75 8.04,39.68
3D3V_S0 on BOTTOM: 5.5,79.05 5.32,79.23 5.32,81.28 5.58,81.54 7.36,81.54 7.86,81.03 7.86,79.25 7.66,79.05
3D3V_S0 on BOTTOM: 45.96,31.73 45.68,32.01 45.68,34.22 45.76,34.29 46.29,34.29 46.73,34.73 47.41,34.73 47.44,34.7 47.74,34.7 47.74,33.71 47.97,33.48 49.01,33.48 49.11,33.58 49.11,34.7 50.18,34.7 50.51,34.37 51.02,34.37 51.2,34.19 51.2,32.31 50.61,31.73 ; 2 cut-outs
3D3V_S0 on L4: 12.22,36.33 32.22,36.33 34.36,34.19 37.53,34.19 38.83,32.9 40.54,32.9 42.27,31.17 45.74,31.17 46.27,31.7 48.68,31.7 48.89,31.91 48.89,32.62 45.83,35.67 45.83,36.58 44.84,37.57 43.83,37.57 42.84,38.56 41.7,38.56 41.7,38.62 40.23,40.09 12.3,40.09 10.63,41.76 10.63,44.07 11.62,45.06 11.62,48.52 10.35,49.79 10.35,54.03 11.24,54.92 11.24,59.52 10.66,60.1 10.63,60.1 10.63,77.88 9.95,78.57 9.95,78.87 7.33,81.49 5.58,81.49 5.37,81.28 5.37,79 7.38,76.99 7.41,76.99 7.41,59.69 8.4,58.7 8.4,58.22 8.25,58.07 8.02,58.07 6.92,56.98 6.92,45.67 6.49,45.24 2.71,45.24 1.23,43.77 1.23,39.45 2.73,37.95 10.59,37.95
3D3V_VGA_S0 on TOP: 49.11,34.8 49.11,38.92 49.44,39.25 50.18,39.25 50.38,39.05 50.38,34.8
3D3V_VGA_S0 on BOTTOM: 49.19,36.02 49.14,36.07 49.14,37.85 49.49,38.2 52.11,38.2 52.34,37.98 52.34,36.15 52.21,36.02
3D3V_VGA_S0 on L4: 50.1,37.36 48.65,37.36 46.52,39.49 46.52,40.01 41.95,44.58 41.95,44.63 40.81,45.77 40.81,46.28 40.43,46.66 39.92,46.66 35.1,51.48 35.1,53.78 35.31,53.99 36.59,53.99 36.6,53.97 36.94,53.97 37.5,53.42 38.03,53.42 38.8,52.64 38.8,50.73 50.27,39.27 50.27,37.52
DCBATOUT on TOP: 38.65,13.26 38.52,13.39 38.52,14.91 38.39,15.04 36.24,15.04 35.98,15.29 35.98,18.6 36.11,18.72 36.74,18.72 37.12,18.34 39.92,18.34 40.43,17.83 40.43,13.64 40.05,13.26
DCBATOUT on TOP: 22.85,13.52 22.57,13.8 20.97,13.8 20.19,14.58 13.11,14.58 12.33,15.36 12.33,27.14 10.58,28.88 5.37,28.88 2.96,31.3 2.96,34.22 2.2,34.98 2.2,36.5 2.58,36.88 7.66,36.88 7.79,36.76 7.79,34.09 7.94,33.94 15.2,33.94 18.68,30.46 18.68,19.33 19.17,18.85 19.22,18.85 21,17.07 22.39,17.07 22.77,17.45 22.77,18.6 22.9,18.72 23.54,18.72 23.66,18.6 23.66,13.64 23.54,13.52 ; 4 cut-outs
DCBATOUT on BOTTOM: 39.92,10.47 37.25,13.14 36.49,13.14 36.11,13.52 36.11,18.6 36.21,18.7 36.85,18.7 36.97,18.57 36.97,17.61 37.38,17.2 38.52,17.2 38.78,17.45 38.78,18.6 38.9,18.72 40.55,18.72 40.68,18.6 40.68,10.98 40.17,10.47 ; 2 cut-outs
DCBATOUT on BOTTOM: 2.28,35 1.92,35.36 1.92,38.94 2.43,39.45 7.41,39.45 7.71,39.14 7.71,35.33 7.38,35
DCBATOUT on BOTTOM: 45.3,7.78 45.15,7.93 45.15,9.48 45.35,9.68 52.54,9.68 52.64,9.58 52.64,7.98 52.44,7.78 ; 2 cut-outs
DCBATOUT on BOTTOM: 22.89,13.53 22.65,13.77 22.65,14.53 22.27,14.91 16.17,14.91 15.92,15.17 15.92,22.66 16.42,23.17 17.31,23.17 19.22,21.26 19.22,19.1 19.98,18.34 22.27,18.34 22.65,18.72 23.54,18.72 23.66,18.6 23.66,13.64 23.55,13.53 ; 3 cut-outs
DCBATOUT on L3: 17.03,15.75 17.03,18.57 17.16,18.7 20.79,18.7 21.5,17.99 23.99,17.99 26.99,14.99 26.99,12.78 27.36,12.41 32.24,12.41 37.66,17.83 39.79,17.83 40.38,17.25 40.38,13.21 41.9,11.69 41.9,9.63 42.87,8.66 45.13,8.66 45.71,9.25 51.45,9.25 51.68,9.02 51.68,7.42 51.04,6.79 41.6,6.79 39.94,8.44 39.94,10.26 39.11,11.1 37.79,11.1 36.77,10.09 25.54,10.09 24.91,10.72 24.91,13.36 23.21,15.07 19.83,15.07 19.47,15.42 17.36,15.42 ; 2 cut-outs
DCBATOUT on L4: 17.06,18.6 17.06,15.8 17.44,15.42 19.47,15.42 19.83,15.07 23.21,15.07 24.91,13.36 24.91,10.72 25.54,10.09 36.77,10.09 37.79,11.1 39.11,11.1 39.94,10.26 39.94,8.49 41.65,6.79 51.02,6.79 51.63,7.39 51.63,9.05 51.43,9.25 45.68,9.25 45.13,8.69 42.84,8.69 41.9,9.63 41.9,11.74 40.43,13.21 40.43,17.2 39.79,17.83 37.66,17.83 32.24,12.41 27.33,12.41 26.99,12.75 26.99,14.99 23.99,17.99 21.5,17.99 20.77,18.72 17.19,18.72 ; 2 cut-outs
FBA_PLL_AVDD on L3 (solid shape): outline of 1155 points within 16.14,59.07 36.83,66.78
FBA_PLL_AVDD on BOTTOM: 13.55,61.45 13.43,61.57 13.43,63.91 14.21,63.91 14.7,63.43 15.08,63.43 15.38,63.73 16.45,63.73 16.68,63.96 16.68,64.67 16.96,64.95 18.35,64.95 18.51,64.8 18.51,61.65 18.3,61.45 ; 4 cut-outs
FBA_PLL_AVDD on L4: 36.26,64.04 35.74,64.56 30.41,64.56 29.58,63.73 28.62,63.73 28.62,63.76 27.24,65.13 16.96,65.13 16.68,64.85 16.65,64.85 16.65,63.02 19.12,60.56 21.88,60.56 22.14,60.3 24.83,60.3 26.41,61.88 34.23,61.88 35.14,60.96 35.14,60.1 36.19,59.06 36.82,59.06 36.87,59.11 36.87,59.67 36.26,60.28
PWR_1D05V_EN on BOTTOM: 2.99,71.83 2.91,71.91 2.91,73.1 2.94,73.13 4.61,73.13 4.79,72.95 4.79,72.09 3.8,72.09 3.55,71.83 ; 1 cut-out
PWR_1D05V_PHASE on BOTTOM: 3.42,68.58 3.06,68.94 3.06,70.84 3.37,71.15 5.12,71.15 5.43,71.45 5.43,72.95 5.5,73.03 6.82,73.03 7.33,72.52 7.33,68.84 7.08,68.58
PWR_1D05V_PVDD on BOTTOM: 6.04,75.21 5.91,75.34 5.91,75.9 6.09,76.08 6.09,77.32 5.5,77.91 5.5,78.67 5.63,78.79 8.42,78.79 8.65,78.57 8.65,75.97 7.89,75.21 ; 5 cut-outs
PWR_1D35V_LDO_P5 on BOTTOM: 47.49,16.51 46.75,17.25 46.75,17.76 47.77,17.76 47.87,17.66 47.87,16.54 47.84,16.51
PWR_1D35V_PHASE on BOTTOM: 48.5,16.54 48.5,17.66 47.08,19.08 47.08,20.7 47.62,21.24 50.71,21.24 51.5,20.45 51.5,17.71 51.31,17.52 49.84,17.52 48.86,16.54 ; 1 cut-out
PWR_DCBATOUT_1D35V on BOTTOM: 49.47,9.86 49.39,9.93 49.39,10.57 49.55,10.72 49.55,14.46 48.99,15.01 48.99,16.26 49.06,16.34 50.84,16.34 52.52,14.66 52.52,10.87 52.54,10.85 52.54,9.88 52.52,9.86 ; 2 cut-outs
PWR_VGA_CORE_PHASE1 on TOP: 34.41,12.32 33.34,13.39 32.76,13.39 32.71,13.44 32.71,19.1 31.82,19.99 31.82,24.57 32.35,25.1 38.14,25.1 38.47,24.77 38.47,20.6 37.46,19.59 36.39,19.59 35.75,18.95 35.75,13.47 35.96,13.26 35.96,12.58 35.7,12.32
PWR_VGA_CORE_PHASE1 on BOTTOM: 34.15,11.26 34.1,11.31 34.1,12.63 33.34,13.39 32.76,13.39 32.68,13.47 32.68,19.15 31.82,20.02 31.82,24.59 32.32,25.1 38.14,25.1 38.47,24.77 38.47,20.6 37.48,19.61 37.48,19.59 36.39,19.59 35.75,18.95 35.75,13.47 35.96,13.26 35.96,12.17 35.04,11.26
PWR_VGA_CORE_PHASE2 on TOP: 23.59,12.37 23.36,12.6 23.36,13.16 23.54,13.34 23.84,13.34 24.04,13.54 24.04,18.85 23.41,19.49 21.5,19.49 21.12,19.87 21.12,24.57 21.63,25.07 27.47,25.07 27.6,24.95 27.6,19.99 26.96,19.36 26.96,13.39 25.95,12.37
PWR_VGA_CORE_PHASE2 on BOTTOM: 24.3,11.23 23.92,11.61 23.92,11.64 23.31,12.25 23.31,13.21 23.41,13.31 23.84,13.31 24.04,13.52 24.04,19.1 23.41,19.74 21.25,19.74 21.12,19.87 21.12,24.54 21.66,25.07 27.47,25.07 27.63,24.92 27.63,20.02 26.96,19.36 26.96,13.39 26.2,13.39 25.82,13.01 25.82,11.36 25.69,11.23
SP_PLLVDD on TOP: 31.82,49 31.23,49.58 31.23,51.9 31.38,52.05 31.77,52.05 32.73,51.08 32.73,49.36 32.38,49 ; 4 cut-outs
SP_PLLVDD on BOTTOM: 31.44,50.88 31,51.31 31,51.79 31.26,52.05 31.77,52.05 32.53,51.29 32.53,50.98 32.43,50.88
VGA_CORE on TOP: 25.31,56.09 25.24,56.16 25.24,56.82 25.34,56.92 34.84,56.92 34.97,56.8 34.97,56.24 34.81,56.09
VGA_CORE on TOP: 33.95,52.45 33.85,52.56 33.85,52.78 33.57,53.06 33.57,53.78 33.7,53.9 33.9,53.9 34.41,53.39 34.41,52.53 34.33,52.45
VGA_CORE on TOP: 17.74,31.83 16.35,33.23 16.35,35.39 18.25,37.29 18.25,48.64 18.56,48.95 31.18,48.95 32.9,47.23 32.9,43.5 36.19,40.21 36.19,33.2 36.15,33.16 36.15,33.04 35.85,32.74 22.01,32.74 21.1,31.83
VGA_CORE on TOP: 24.79,58.31 24.54,58.56 24.54,61.66 24.97,62.09 34.24,62.09 34.51,61.83 34.51,61.22 34.94,60.79 34.94,60.68 34.76,60.51 25.14,60.51 25.01,60.38 25.01,59.59 25.26,59.34 34.36,59.34 34.92,58.78 34.92,58.55 34.67,58.31 ; 22 cut-outs
VGA_CORE on TOP: 30.98,52.43 30.62,52.78 26.91,52.78 26.56,53.14 25.92,53.14 25.62,53.44 25.62,53.72 25.75,53.85 31.77,53.85 31.84,53.78 31.84,52.51 31.77,52.43 ; 2 cut-outs
VGA_CORE on BOTTOM: outline of 83 points within 25.46,52.81 35.05,62.97
VGA_CORE on BOTTOM: 17.08,28.32 14.82,30.58 14.82,33.3 18.38,36.86 20.87,36.86 20.92,36.91 35.68,36.91 36.69,35.89 36.69,34.27 37.35,33.61 37.35,28.96 36.72,28.32
VGA_CORE on L3: 31.54,61.75 34.08,61.75 35.19,60.63 35.19,49.13 31.28,45.22 24.58,45.22 23.94,45.85 20.74,45.85 18.3,48.29 18.3,58.52 19.6,59.82 25.49,59.82 28.5,62.83 30.86,62.83 31.13,62.56 31.13,62.16
VGA_CORE on L4: 25.06,45.85 25.06,51.74 25.42,52.1 25.42,60.33 26.27,61.18 34.65,61.18 35.03,60.8 35.03,59.58 35.19,59.41 35.19,54.69 34.89,54.38 34.89,51.21 35.19,50.9 35.19,49.13 35.18,49.11 35.18,48.28 32.17,45.27 25.64,45.27
VGA_CORE on L5VCC: 25.27,45.2 25,45.47 25,51.54 25.63,52.17 25.63,60.43 26.28,61.08 35.01,61.08 35.28,60.81 35.28,48.9 31.58,45.2
VGA_CORE on L6: 21.66,32.59 35.65,32.59 36.06,33 36.06,37.77 33.8,40.03 33.8,50.98 33.09,51.69 33.09,62.36 32.65,62.79 27.96,62.79 27.19,62.03 18.89,62.03 17.63,60.77 17.63,50.92 16.5,49.79 16.5,35.44 16.32,35.26 16.32,33.28 17.72,31.88 20.95,31.88

Small or netless copper shapes (teardrops, artwork), in the pictures only: 3 on BOTTOM

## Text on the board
Ref Des/Silkscreen Bottom: M2L2 | X7601:27MHZ
Ref Des/Silkscreen Top: YDRF2 | 15896-1 | Starlord17 GPU | MADE IN TAIWAN
User.27: Board Accuracy Check,Jan 13 15:51:33 2016,Passed | Dummy-Static-No Shape On Layer Check,Jan 13 15:51:35 2016,Passed | Split Plane Check,Oct 21 17:05:09 2015,Passed
User.29: ByImpedance:100.0@_REF_L1=("nil(L1)")|_REF_L6=("4.0/10.0(L6)")|Type="DP"|_REF_L4=("4.0/6.5(L4)")|_REF_L3=("4.0/6.5(L3)" "4.0/10.0(L3)")|imp="100.0"|_REF_L8=("nil(L8)") | ByImpedance:33.0@_REF_L1=("8.0(L1)")|_REF_L6=("9.0(L6)")|Type="SE"|_REF_L4=("11.0(L4)")|_REF_L3=("11.0(L3)" "9.0(L3)")|imp="33.0"|_REF_L8=("8.0(L8)") | ByImpedance:35.0@_REF_L1=("7.5(L1)")|_REF_L6=("8.5(L6)")|Type="SE"|_REF_L4=("10.0(L4)")|_REF_L3=("10.0(L3)" "8.5(L3)")|imp="35.0"|_REF_L8=("7.5(L8)") | ByImpedance:37.5@_REF_L1=("6.5(L1)")|_REF_L6=("7.5(L6)")|Type="SE"|_REF_L4=("9.0(L4)")|_REF_L3=("7.5(L3)" "9.0(L3)")|imp="37.5"|_REF_L8=("6.5(L8)") | ByImpedance:40.0@_REF_L1=("6.0(L1)")|_REF_L6=("6.5(L6)")|Type="SE"|_REF_L4=("8.0(L4)")|_REF_L3=("6.5(L3)" "8.0(L3)")|imp="40.0"|_REF_L8=("6.0(L8)") | ByImpedance:45.0@_REF_L1=("4.5(L1)")|_REF_L6=("5.0(L6)")|Type="SE"|_REF_L4=("6.5(L4)")|_REF_L3=("6.5(L3)" "5.0(L3)")|imp="45.0"|_REF_L8=("4.5(L8)") | ByImpedance:50.0@_REF_L1=("3.5(L1)")|_REF_L6=("4.0(L6)")|Type="SE"|_REF_L4=("5.0(L4)")|_REF_L3=("4.0(L3)" "5.0(L3)")|imp="50.0"|_REF_L8=("3.5(L8)") | ByImpedance:55.0@_REF_L1=("nil(L1)")|_REF_L6=("nil(L6)")|Type="SE"|_REF_L4=("4.0(L4)")|_REF_L3=("4.0(L3)")|imp="55.0"|_REF_L8=("nil(L8)") | ByImpedance:60.0@_REF_L1=("7.5/4.0(L1)")|_REF_L6=("9.5/4.5(L6)")|Type="DP"|_REF_L4=("10.5/4.5(L4)")|_REF_L3=("10.5/4.5(L3)" "9.5/4.5(L3)")|imp="60.0"|_REF_L8=("7.5/4.0(L8)") | ByImpedance:63.0@_REF_L1=("7.0/4.5(L1)")|_REF_L6=("8.5/4.0(L6)")|Type="DP"|_REF_L4=("9.5/4.0(L4)")|_REF_L3=("8.5/4.0(L3)" "9.5/4.0(L3)")|imp="63.0"|_REF_L8=("7.0/4.5(L8)") | ByImpedance:70.0@_REF_L1=("6.0/5.0(L1)")|_REF_L6=("7.0/5.0(L6)")|Type="DP"|_REF_L4=("8.5/5.0(L4)")|_REF_L3=("7.0/5.0(L3)" "8.5/5.0(L3)")|imp="70.0"|_REF_L8=("6.0/5.0(L8)") | ByImpedance:72.0@_REF_L1=("5.5/4.5(L1)")|_REF_L6=("6.5/4.5(L6)")|Type="DP"|_REF_L4=("7.5/5.0(L4)")|_REF_L3=("7.5/5.0(L3)" "6.5/4.5(L3)")|imp="72.0"|_REF_L8=("5.5/4.5(L8)") | ByImpedance:75.0@_REF_L1=("5.0/4.5(L1)")|_REF_L6=("6.0/4.5(L6)")|Type="DP"|_REF_L4=("7.0/5.0(L4)")|_REF_L3=("7.0/5.0(L3)" "6.0/4.5(L3)")|imp="75.0"|_REF_L8=("5.0/4.5(L8)") | ByImpedance:80.0@_REF_L1=("4.5/5.0(L1)")|_REF_L6=("5.5/5.0(L6)")|Type="DP"|_REF_L4=("6.0/5.0(L4)")|_REF_L3=("5.5/5.0(L3)" "6.0/5.0(L3)")|imp="80.0"|_REF_L8=("4.5/5.0(L8)") | ByImpedance:83.0@_REF_L1=("3.5/4.0(L1)")|_REF_L6=("5.0/4.0(L6)")|Type="DP"|_REF_L4=("5.5/4.5(L4)")|_REF_L3=("5.5/4.5(L3)" "5.0/4.0(L3)")|imp="83.0"|_REF_L8=("3.5/4.0(L8)") | ByImpedance:85.0@_REF_L1=("4.0/5.0(L1)")|_REF_L6=("5.0/5.5(L6)")|Type="DP"|_REF_L4=("5.5/5.0(L4)")|_REF_L3=("5.5/5.0(L3)" "5.0/5.5(L3)")|imp="85.0"|_REF_L8=("4.0/5.0(L8)") | ByImpedance:88.0@_REF_L1=("4.0/7.0(L1)")|_REF_L6=("4.0/4.0(L6)")|Type="DP"|_REF_L4=("5.0/5.0(L4)")|_REF_L3=("4.0/4.0(L3)" "5.0/5.0(L3)")|imp="88.0"|_REF_L8=("4.0/7.0(L8)") | ByImpedance:90.0@_REF_L1=("4.0/8.0(L1)" "3.5/6.0(L1)")|_REF_L6=("4.0/4.5(L6)")|Type="DP"|_REF_L4=("5.0/6.0(L4)")|_REF_L3=("5.0/6.0(L3)" "4.0/4.5(L3)")|imp="90.0"|_REF_L8=("4.0/8.0(L8)" "3.5/6.0(L8)") | LayerIndex:nil | Source:8-1.0-16f.xls | artWorks:("_REF_L3" "_REF_L6" "_REF_L4" "_REF_L8" "_REF_L1") | gtImpOutlineUsed:BOARD GEOMETRY/PANEL_OUTLINE
User.31: This gerber is just for your reference to find the DP impedance traces in layer L1. | DP IMPEDANCE TABLE: L1 | * - Denotes that this Impedance | is NOT used | IMP(Ohm) | *60.0 | *63.0 | *70.0 | *72.0 | *75.0 | 80.0 | *83.0 | *85.0 | *88.0 | *90.0 | *100.0 | WIDTH(mils) | 7.5/4.0 | 7.0/4.5 | 6.0/5.0 | 5.5/4.5 | 5.0/4.5 | 4.5/5.0 | 3.5/4.0 | 4.0/5.0 | 4.0/7.0 | 4.0/8.0 | 3.5/6.0 | nil | TYPE | DP
User.33: This gerber is just for your reference to find the SE impedance traces in layer L1. | SE IMPEDANCE TABLE: L1 | * - Denotes that this Impedance | is NOT used | IMP(Ohm) | *33.0 | *35.0 | *37.5 | *40.0 | 45.0 | 50.0 | *55.0 | WIDTH(mils) | 8.0 | 7.5 | 6.5 | 6.0 | 4.5 | 3.5 | nil | TYPE | SE
User.35: This gerber is just for your reference to find the DP impedance traces in layer L3. | DP IMPEDANCE TABLE: L3 | * - Denotes that this Impedance | is NOT used | IMP(Ohm) | *60.0 | *63.0 | *70.0 | *72.0 | *75.0 | 80.0 | *80.0 | *83.0 | *85.0 | *88.0 | *90.0 | *100.0 | WIDTH(mils) | 10.5/4.5 | 9.5/4.5 | 8.5/4.0 | 9.5/4.0 | 7.0/5.0 | 8.5/5.0 | 7.5/5.0 | 6.5/4.5 | 6.0/4.5 | 5.5/5.0 | 6.0/5.0 | 5.5/4.5 | 5.0/4.0 | 5.0/5.5 | 4.0/4.0 | 5.0/5.0 | 5.0/6.0 | 4.0/4.5 | 4.0/6.5 | 4.0/10.0 | TYPE | DP
User.37: This gerber is just for your reference to find the SE impedance traces in layer L3. | SE IMPEDANCE TABLE: L3 | * - Denotes that this Impedance | is NOT used | IMP(Ohm) | *33.0 | *35.0 | *37.5 | *40.0 | *45.0 | 45.0 | 50.0 | *50.0 | *55.0 | WIDTH(mils) | 11.0 | 9.0 | 10.0 | 8.5 | 7.5 | 6.5 | 8.0 | 5.0 | 4.0 | TYPE | SE
User.39: This gerber is just for your reference to find the DP impedance traces in layer L4. | DP IMPEDANCE TABLE: L4 | * - Denotes that this Impedance | is NOT used | IMP(Ohm) | *60.0 | *63.0 | *70.0 | *72.0 | *75.0 | *80.0 | *83.0 | *85.0 | *88.0 | *90.0 | *100.0 | WIDTH(mils) | 10.5/4.5 | 9.5/4.0 | 8.5/5.0 | 7.5/5.0 | 7.0/5.0 | 6.0/5.0 | 5.5/4.5 | 5.5/5.0 | 5.0/5.0 | 5.0/6.0 | 4.0/6.5 | TYPE | DP
User.41: This gerber is just for your reference to find the SE impedance traces in layer L4. | SE IMPEDANCE TABLE: L4 | * - Denotes that this Impedance | is NOT used | IMP(Ohm) | *33.0 | *35.0 | *37.5 | *40.0 | *45.0 | *50.0 | *55.0 | WIDTH(mils) | 11.0 | 10.0 | 9.0 | 8.0 | 6.5 | 5.0 | 4.0 | TYPE | SE
User.43: This gerber is just for your reference to find the DP impedance traces in layer L6. | DP IMPEDANCE TABLE: L6 | * - Denotes that this Impedance | is NOT used | IMP(Ohm) | *60.0 | *63.0 | *70.0 | *72.0 | *75.0 | 80.0 | *83.0 | *85.0 | *88.0 | *90.0 | *100.0 | WIDTH(mils) | 9.5/4.5 | 8.5/4.0 | 7.0/5.0 | 6.5/4.5 | 6.0/4.5 | 5.5/5.0 | 5.0/4.0 | 5.0/5.5 | 4.0/4.0 | 4.0/4.5 | 4.0/10.0 | TYPE | DP
User.45: Note:Refer to DRILL layer for ELLIPSE drill direction | FIGURE | SIZE | 10.0 | 16.0 | 178.0 | 229.0 | 28.0 | 86.0 | 91.0 | 107.0 | 113.0 | 123.0x103.0 | DRILL CHART: TOP to BOTTOM | ALL UNITS ARE IN MILS | PLATED | NON-PLATED | QTY | 959 | 268 | 4 | 1 | 10 | 2 | This gerber is just for your reference to find the DP impedance traces in layer L8. | This gerber is just for your reference to find the SE impedance traces in layer L6. | This gerber is just for your reference to find the SE impedance traces in layer L8. | DP IMPEDANCE TABLE: L8 | SE IMPEDANCE TABLE: L6 | SE IMPEDANCE TABLE: L8 | * - Denotes that this Impedance | is NOT used | Starlord17 GPU | Model | PCB_NO | 15896 | VER. | Layer | DRILL | L1 | L2GND | L3 | L4 | TMASK | TPLACE | TSILK | TSMD | IMP(Ohm) | *33.0 | *60.0 | *35.0 | *63.0 | *37.5 | *70.0 | *40.0 | *72.0 | *75.0 | 45.0 | 50.0 | 80.0 | *55.0 | *83.0 | *85.0 | *88.0 | *90.0 | 90.0 | *100.0 | Designer | Ada | WIDTH(mils) | 8.0 | 9.0 | 7.5 | 8.5 | 6.5 | 6.0 | 4.5 | 5.0 | 3.5 | 4.0 | nil | 7.5/4.0 | 7.0/4.5 | 6.0/5.0 | 5.5/4.5 | 5.0/4.5 | 4.5/5.0 | 3.5/4.0 | 4.0/5.0 | 4.0/7.0 | 4.0/8.0 | 3.5/6.0 | Date | 02/25/2016 | TYPE | SE | DP | BMASK | BPLACE | BSILK | BSMD | L5VCC | L6 | L7GND | L8
